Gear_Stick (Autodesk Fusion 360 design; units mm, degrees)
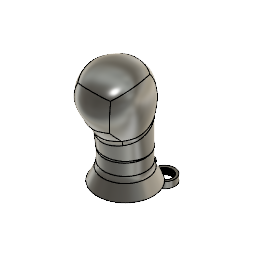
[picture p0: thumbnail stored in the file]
sphere_primitive "SpherePrimitive1" Diameter 45
split "Split1"
move_face "MoveFace1"
cylinder_primitive "CylinderPrimitive1" Height 35 Diameter 33
move_face "MoveFace2"
copy_paste_bodies "CopyPasteBodies1"
move "Move1"
extrude "Extrude1" add of existing geometry blind 10
work_plane "WorkPlane1" AlongDistance 45
move "Move2"
split "Split2"
extrude "Extrude3" add of existing geometry blind 5
move_face "MoveFace4"
loft "Loft2"
form "Form1"
work_plane "WorkPlane2" AlongDistance 15
split "Split3"
extrude "Extrude5" cut of existing geometry blind -10
work_plane "WorkPlane3" AlongDistance 59.5
work_plane "WorkPlane4" AlongDistance 20
work_plane "WorkPlane5" RotateAngle 15
work_plane "WorkPlane6" AlongDistance 55
split "Split4"
loft "Loft7"
sketch "Sketch5" plane through (0, 5.6, 99.5) normal (0, 0, 1) x axis (1, 0, 0)
extrude "Extrude6" cut of existing geometry blind -6
cylinder_primitive "CylinderPrimitive2" Height -37 Diameter 21.5
cylinder_primitive "CylinderPrimitive3" Height -30 Diameter 11.6
chamfer "Chamfer1" distance 5.8
chamfer "Chamfer2" distance 4.95
sketch "Sketch8" plane through (0, 0, 16) normal (0, 0, -1) x axis (1, 0, 0)
  circle C1 centre (0, -5.6) radius 10.75
  circle C2 centre (0, -5.6) radius 16.5
  circle C3 centre (0, -5.6) radius 22.5
  dimension "d34" diameter C3 = 45
extrude "Extrude7" new body sketch "Sketch8" profile of C2 C3 against normal blind 24
work_plane "WorkPlane7" AlongDistance -12
split "Split5"
draft "Draft1" Angle1 25 Angle2 0
combine "Combine3"
fillet "Fillet7" radius 10
cylinder_primitive "CylinderPrimitive4" Height 5 Diameter 16
copy_paste_bodies "CopyPasteBodies2"
move "Move3"
hole "Hole1" HoleDepth 8 HoleDiameter 10.274 TipAngle 180
delete_face "DeleteFace1"
chamfer "Chamfer3" distance 0.45
chamfer "Chamfer4" distance 0.44
hole "Hole2" HoleDepth 8 HoleDiameter 12 TipAngle 180
fillet "Fillet10" radius 10
fillet "Fillet11" radius 10
hole "Hole3" HoleDepth 30 HoleDiameter 10.274 TipAngle 90 CSDiameter 21.5 CSAngle 90
delete_face "DeleteFace2"
chamfer "Chamfer5" distance 0.45
chamfer "Chamfer6" distance 0.44
offset_faces "OffsetFaces1" distance 0.08
offset_faces "OffsetFaces2" distance 0.1
delete_face "DeleteFace3"
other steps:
base_feature "Base Feature1"
base_feature "Base Feature2"
thread "Thread1"
thread "Thread2"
